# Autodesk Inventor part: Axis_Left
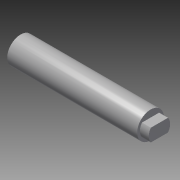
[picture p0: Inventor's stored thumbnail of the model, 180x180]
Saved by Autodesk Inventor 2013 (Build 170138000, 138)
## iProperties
Created: 2006-03
Part Number: Axis_Left
Document SubType Name: Modeling
Designer: debonom
Material: Stainless Steel, 440C
Mass: 103.094 g
Surface Area: 39.6652 cm^2
Volume: 13.3025 cm^3
Density: 7.75 g/cm^3
Author: debonom
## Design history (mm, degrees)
sketch "Sketch1"
  geometry: L1 (-4.823, 3.575)-(4.823, 3.575); L2 (4.823, 3.575)-(4.823, -3.575); L3 (4.823, -3.575)-(-4.822, -3.575); L4 (-4.822, -3.575)-(-4.823, 3.575); L5 (-4.823, 3.575)-(4.823, -3.575); L6 (-8.405, 0)-(8.405, 0) reference; A1 r 6 centre (-0.004, 0) between (-4.823, 3.575) and (-4.822, -3.575); A2 r 6 centre (0.004, 0) between (4.823, -3.575) and (4.823, 3.575); 2 further points
  constraints: 10 end point, 4 point on circle, 2 centre point, 2 parallel, 2 point on line, 1 coincident, 1 equal radius, 1 horizontal, 1 midpoint, 1 perpendicular
  dimensions: "d0" = 9.645 distance of L2.end L3.end; "d1" = 7.15 distance of L3.end L1.start; "d2" = 6 radius of A1
extrude "Extrusion1" new body sketch "Sketch1" distance "d3" = 5; taper "d4" = 0 deg
sketch "Sketch2"
  geometry: C1 r 7.5 at (0, 0); 1 further point
  constraints: 1 centre point, 1 coincident
  dimensions: "d5" = 15 diameter of C1
extrude "Extrusion2" join sketch "Sketch2" distance "d6" = 73; taper "d7" = 0 deg
body "Solid1"
